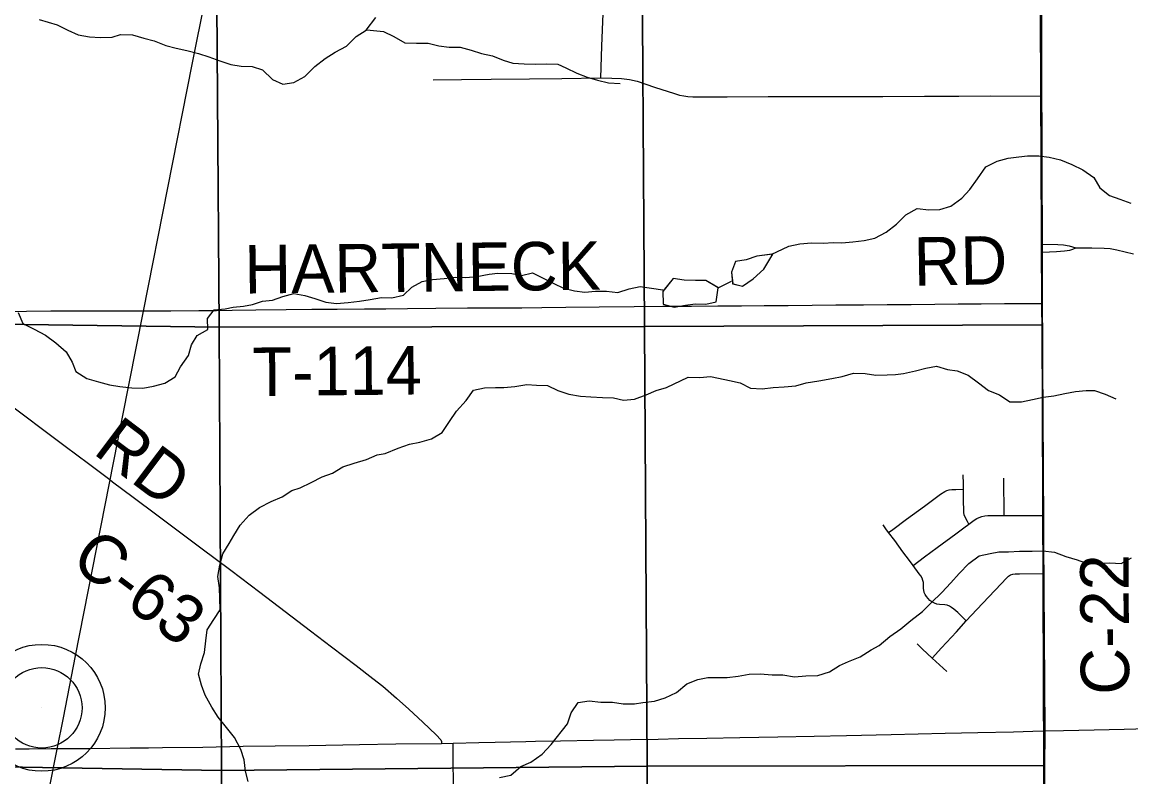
# Model space of a CAD drawing. Extents: x 0 to 34, y 0 to 22.
# Drawn here: x 3.679 to 4.329, y 19.103 to 19.545 of the extents above; entities that cross this region are included whole.
import ezdxf

# ---------------------------------------------------------------- set-up
doc = ezdxf.new("R2010")
doc.units = 0
for name, color, linetype in [('GM_X_County_Road', 7, 'Continuous'), ('GM_X_County_Road_Text', 7, 'Continuous'), ('GM_X_Minor_Lake', 7, 'Continuous'), ('GM_X_Minor_River', 7, 'Continuous'), ('GM_X_Rail_Line', 7, 'Continuous'), ('GM_X_Rail_Line_Text', 7, 'Continuous'), ('GM_X_Section', 7, 'Continuous'), ('GM_X_State_Route', 7, 'Continuous'), ('GM_X_Township', 7, 'Continuous'), ('GM_X_Township_Road', 7, 'Continuous'), ('GM_X_Township_Road_Text', 7, 'Continuous'), ('GM_X_Unincorporated', 7, 'Continuous'), ('GM_X_Unincorporated_Location', 7, 'Continuous')]:
    doc.layers.add(name, color=color, linetype=linetype)

msp = doc.modelspace()

# ---------------------------------------------------------------- linework, layer by layer
at = {"layer": 'GM_X_County_Road'}
for points in [[(4.27842, 19.13012), (4.27823, 19.14942), (4.27809, 19.18871), (4.27797, 19.20548), (4.27788, 19.22223), (4.2778, 19.2563), (4.27762, 19.27909), (4.2775, 19.31971), (4.27734, 19.34088), (4.27721, 19.35817), (4.27715, 19.38057), (4.27709, 19.39599), (4.27715, 19.41065), (4.27709, 19.41525), (4.27698, 19.42412), (4.27692, 19.45257), (4.27688, 19.46599), (4.2768, 19.48305), (4.27668, 19.50205), (4.27661, 19.57053)], [(3.62487, 19.35626), (3.63776, 19.34669), (3.64483, 19.34139), (3.65541, 19.33346), (3.66879, 19.32344), (3.67892, 19.31584), (3.69228, 19.30583), (3.70416, 19.29693), (3.71775, 19.28674), (3.73032, 19.27732), (3.73192, 19.27613)], [(3.73192, 19.27613), (3.74392, 19.26714), (3.75775, 19.25679), (3.7703, 19.24735), (3.78355, 19.23738), (3.80121, 19.22424), (3.81825, 19.21133), (3.83298, 19.20001), (3.84797, 19.18864), (3.86027, 19.17931), (3.87466, 19.16833), (3.88453, 19.16072), (3.89027, 19.15624), (3.89839, 19.14931), (3.90547, 19.14285), (3.9137, 19.1351), (3.92154, 19.12774), (3.9243, 19.12491), (3.92472, 19.12386), (3.92474, 19.12263)], [(4.27851, 19.09573), (4.27854, 19.11102), (4.27846, 19.12439), (4.27842, 19.13012)]]:
    msp.add_lwpolyline(points, dxfattribs=at)
at = {"layer": 'GM_X_Minor_Lake'}
for points in [[(4.11904, 19.40958), (4.10953, 19.40825), (4.10326, 19.40619), (4.09717, 19.40509), (4.09467, 19.39901), (4.09544, 19.39219)], [(4.11839, 19.40949), (4.10953, 19.40825), (4.10326, 19.40619), (4.09717, 19.40509), (4.09467, 19.39901), (4.0954, 19.39254)], [(4.0952, 19.39225), (4.10128, 19.3908), (4.10738, 19.39495), (4.11367, 19.40062), (4.11899, 19.40949)], [(4.09544, 19.39219), (4.10128, 19.3908), (4.10738, 19.39495), (4.11367, 19.40062), (4.11904, 19.40958)], [(4.05456, 19.3879), (4.0547, 19.38021), (4.06115, 19.37846), (4.0678, 19.37957), (4.0735, 19.3803), (4.07977, 19.38026), (4.08585, 19.38156), (4.08687, 19.38968)], [(4.08688, 19.38976), (4.07965, 19.39396), (4.07357, 19.39399), (4.06692, 19.39422), (4.06047, 19.39521), (4.05457, 19.38765)], [(4.05457, 19.38765), (4.0547, 19.38021), (4.06115, 19.37846), (4.0678, 19.37957), (4.0735, 19.3803), (4.07977, 19.38026), (4.08585, 19.38156), (4.08688, 19.38976)], [(4.08667, 19.38988), (4.07965, 19.39396), (4.07357, 19.39399), (4.06692, 19.39422), (4.06047, 19.39521), (4.05476, 19.3879)]]:
    msp.add_lwpolyline(points, dxfattribs=at)
at = {"layer": 'GM_X_Minor_River'}
for points in [[(3.68876, 19.54705), (3.6994, 19.54387), (3.70565, 19.5408), (3.71171, 19.5381), (3.71836, 19.53692), (3.72481, 19.5365), (3.73165, 19.53666), (3.73659, 19.53815), (3.74362, 19.53811), (3.75026, 19.53617), (3.75633, 19.53443), (3.76315, 19.53173), (3.76922, 19.53017), (3.77548, 19.5288), (3.78231, 19.52705), (3.78838, 19.52512), (3.79483, 19.5228), (3.80127, 19.52067), (3.80735, 19.51969), (3.8138, 19.51946), (3.81987, 19.51753), (3.82573, 19.51179), (3.83179, 19.50909), (3.83807, 19.51001), (3.84454, 19.51359), (3.85046, 19.51945), (3.85656, 19.52417), (3.86247, 19.52794), (3.86894, 19.53133), (3.87467, 19.53701), (3.88057, 19.54078), (3.88623, 19.5482)], [(3.88088, 19.54097), (3.89064, 19.53996), (3.8967, 19.53708), (3.90314, 19.53343), (3.90998, 19.5332), (3.91681, 19.53316), (3.92307, 19.5316), (3.92915, 19.53081), (3.9356, 19.53077), (3.94205, 19.52903), (3.94812, 19.52709), (3.95457, 19.52572), (3.96083, 19.52321), (3.96651, 19.52147), (3.97316, 19.52105), (3.97962, 19.52083), (3.98646, 19.52098), (3.99291, 19.52075), (3.99765, 19.51864), (4.00409, 19.51556), (4.01016, 19.51324), (4.01623, 19.51149), (4.02268, 19.50994), (4.02951, 19.50952)], [(4.11799, 19.40929), (4.12837, 19.41424), (4.13483, 19.41553), (4.14167, 19.41606), (4.14851, 19.41603), (4.15459, 19.41637), (4.15934, 19.41616), (4.1658, 19.41669), (4.17245, 19.41742), (4.17872, 19.4189), (4.18539, 19.42229), (4.19149, 19.42701), (4.19702, 19.4325), (4.2035, 19.43627), (4.21052, 19.43547), (4.21698, 19.43562), (4.22326, 19.43768), (4.22974, 19.4424), (4.23451, 19.44732), (4.23891, 19.45357), (4.24389, 19.46058), (4.25055, 19.46397), (4.25702, 19.46584), (4.26329, 19.46656), (4.26823, 19.46711), (4.27488, 19.46707), (4.28095, 19.46628), (4.28759, 19.46472), (4.29422, 19.46202), (4.30067, 19.45894), (4.3071, 19.45434), (4.31068, 19.44842), (4.31635, 19.44382), (4.32242, 19.4417), (4.32887, 19.43938)], [(3.9024, 19.38543), (3.90736, 19.39016), (3.91346, 19.39355), (3.91954, 19.39466), (3.92638, 19.39519), (3.93284, 19.3961), (3.93892, 19.39588), (3.94538, 19.39641), (3.9526, 19.39771), (3.95773, 19.39844), (3.9659, 19.3982), (3.97159, 19.39703), (3.97806, 19.39852), (3.98393, 19.39563), (3.99056, 19.39236), (3.99624, 19.38948), (4.00269, 19.38792), (4.00877, 19.38712), (4.01504, 19.38785), (4.0215, 19.38781), (4.02814, 19.38702), (4.0348, 19.38907), (4.04126, 19.39056), (4.05456, 19.3885)], [(4.08687, 19.38968), (4.0948, 19.39364)], [(3.67653, 19.37526), (3.67934, 19.36878), (3.68597, 19.36551), (3.6926, 19.36205), (3.69866, 19.35745), (3.70471, 19.35228), (3.7081, 19.34617), (3.71035, 19.34064), (3.71679, 19.33661), (3.72362, 19.33467), (3.73006, 19.33293), (3.73614, 19.33194), (3.74316, 19.33114), (3.74962, 19.33091), (3.75589, 19.33221), (3.76255, 19.33389), (3.76864, 19.33766), (3.77171, 19.34354), (3.7763, 19.35017), (3.77823, 19.35625), (3.78149, 19.36175), (3.78777, 19.36533), (3.78762, 19.3718), (3.79144, 19.37691), (3.7979, 19.37744), (3.80265, 19.37837), (3.80873, 19.3791), (3.81387, 19.38002), (3.81976, 19.38189), (3.82565, 19.38262), (3.83174, 19.38468), (3.83821, 19.38635), (3.84466, 19.38518), (3.85054, 19.38343), (3.85699, 19.3813), (3.86325, 19.38051), (3.87009, 19.38123), (3.87674, 19.38196), (3.88283, 19.38287), (3.88948, 19.38417), (3.89556, 19.38394), (3.9024, 19.38543)], [(3.81133, 19.10039), (3.80984, 19.10649), (3.80893, 19.11315), (3.80706, 19.11925), (3.80329, 19.12612), (3.79876, 19.13204), (3.79386, 19.13816), (3.79009, 19.14407), (3.78614, 19.15094), (3.78407, 19.15685), (3.78221, 19.16333), (3.78357, 19.16941), (3.78569, 19.17606), (3.78648, 19.1829), (3.78728, 19.18936), (3.79129, 19.19543), (3.79493, 19.20112), (3.79477, 19.20759), (3.79462, 19.21386), (3.79351, 19.22053), (3.79468, 19.22718), (3.79661, 19.23383), (3.80025, 19.23989), (3.80294, 19.24464), (3.80676, 19.2507), (3.81192, 19.25657), (3.81802, 19.26091), (3.82488, 19.26449), (3.83135, 19.26731), (3.83706, 19.27089), (3.84182, 19.27257), (3.84829, 19.27558), (3.85477, 19.27897), (3.86086, 19.28122), (3.86695, 19.2848), (3.87342, 19.28705), (3.88065, 19.2891), (3.88693, 19.29192), (3.89168, 19.29265), (3.89929, 19.29585), (3.90595, 19.29809), (3.91204, 19.29939), (3.91888, 19.30125), (3.92517, 19.30502), (3.92938, 19.31147), (3.93359, 19.31753), (3.93913, 19.32378), (3.94353, 19.32984), (3.94999, 19.33114), (3.95645, 19.33129), (3.9612, 19.33127), (3.96766, 19.33199), (3.97469, 19.3331), (3.98039, 19.33268), (3.98684, 19.33246), (3.99291, 19.32957), (3.99935, 19.32744), (4.00618, 19.32626), (4.01226, 19.32585), (4.0191, 19.32543), (4.02555, 19.3252), (4.03143, 19.32384), (4.03789, 19.32457), (4.04474, 19.327), (4.05065, 19.32963), (4.05673, 19.33131), (4.0693, 19.33733), (4.07613, 19.33729), (4.0824, 19.33783), (4.08715, 19.33685), (4.0936, 19.33548), (4.09986, 19.33412), (4.10592, 19.33104), (4.11276, 19.33062), (4.11922, 19.33134), (4.12568, 19.33169), (4.13252, 19.33222), (4.1386, 19.33409), (4.14602, 19.33519), (4.15362, 19.33667), (4.1597, 19.33778), (4.16636, 19.33983), (4.1732, 19.33961), (4.17946, 19.33862), (4.18592, 19.33877), (4.19086, 19.33894), (4.19561, 19.33948), (4.20264, 19.34116), (4.20873, 19.34264), (4.215, 19.34375)], [(4.215, 19.34375), (4.22145, 19.34181), (4.22714, 19.34102), (4.23359, 19.33851), (4.23965, 19.3341), (4.24551, 19.3295), (4.25195, 19.327), (4.25801, 19.32297), (4.26485, 19.32293), (4.27131, 19.32423), (4.2774, 19.32571), (4.28367, 19.32644), (4.29013, 19.32774), (4.29641, 19.32903), (4.30268, 19.32957), (4.30762, 19.32954), (4.31387, 19.32741), (4.32013, 19.32472)], [(3.95873, 19.10281), (3.96538, 19.10411), (3.9713, 19.10921), (3.97719, 19.11165), (3.98368, 19.11637), (3.98902, 19.12205), (3.99858, 19.13417), (4.0007, 19.14063), (4.00491, 19.14669), (4.01137, 19.14761), (4.01821, 19.147), (4.02504, 19.14696), (4.03131, 19.14597), (4.03795, 19.14594), (4.0427, 19.14667), (4.04955, 19.14759), (4.05582, 19.14945), (4.06249, 19.15265), (4.06859, 19.15775), (4.07506, 19.16019), (4.08095, 19.1613), (4.08741, 19.16145), (4.09216, 19.16143), (4.09862, 19.16215), (4.10508, 19.16326), (4.11154, 19.1636), (4.11857, 19.16299), (4.12483, 19.16296), (4.13167, 19.16178), (4.13832, 19.16231), (4.14534, 19.16246), (4.15219, 19.16471), (4.1581, 19.16848), (4.16343, 19.17073), (4.17009, 19.17355), (4.17657, 19.17751), (4.18133, 19.18015), (4.18762, 19.18544), (4.1941, 19.18997), (4.19982, 19.19469), (4.20669, 19.19998), (4.21184, 19.20509), (4.21814, 19.21114), (4.2233, 19.21682), (4.22826, 19.22231), (4.2338, 19.22818), (4.2399, 19.23271), (4.24636, 19.234), (4.2515, 19.23512), (4.25719, 19.23508), (4.26365, 19.23543), (4.27106, 19.23539), (4.27733, 19.23554), (4.28416, 19.23475), (4.2908, 19.23223), (4.29743, 19.2303), (4.30331, 19.22817), (4.30977, 19.22813), (4.31661, 19.22848), (4.32325, 19.22825), (4.32935, 19.23145)]]:
    msp.add_lwpolyline(points, dxfattribs=at)
at = {"layer": 'GM_X_Rail_Line'}
msp.add_lwpolyline([(3.68321, 18.51252), (3.68335, 18.52615), (3.68363, 18.60767), (3.68539, 18.8321), (3.68546, 18.87311), (3.68595, 18.92557), (3.68616, 18.95267), (3.68616, 18.97444), (3.68667, 19.02131), (3.6878, 19.04242), (3.68925, 19.05702), (3.69052, 19.0684), (3.69255, 19.08272), (3.69485, 19.09663), (3.69943, 19.11938), (3.70316, 19.13778), (3.71011, 19.17401), (3.73756, 19.31305), (3.74992, 19.37604), (3.77857, 19.5207), (3.78644, 19.55974)], dxfattribs=at)
at = {"layer": 'GM_X_Rail_Line_Text'}
msp.add_lwpolyline([(2.77875, 17.80661), (3.04126, 17.80913), (3.53178, 17.8199), (4.04512, 17.83208), (4.17864, 17.83524), (4.28678, 17.83811), (4.28692, 17.84212), (4.28581, 17.95524), (4.28464, 18.15407), (4.27642, 18.36992), (4.27726, 18.56476), (4.27587, 18.8261), (4.27859, 19.13014), (4.27679, 19.3807), (4.2769, 19.4129), (4.27672, 19.50175), (4.27627, 19.60888)], dxfattribs=at)
at = {"layer": 'GM_X_Section'}
for points in [[(3.79246, 19.63723), (3.79428, 19.36662), (3.53702, 19.37026), (3.53581, 19.63725)], [(4.04196, 19.63655), (4.0438, 19.36716), (3.79428, 19.36662), (3.79246, 19.63723)], [(4.27537, 19.63561), (4.27657, 19.37662), (4.2766, 19.36802), (4.0438, 19.36716), (4.04196, 19.63655)], [(3.79428, 19.36662), (3.79582, 19.10682), (3.53903, 19.11114), (3.53702, 19.37026)], [(4.0438, 19.36716), (4.04538, 19.10932), (3.79582, 19.10682), (3.79428, 19.36662)], [(4.2766, 19.36802), (4.2777, 19.10976), (4.04538, 19.10932), (4.0438, 19.36716)], [(3.79582, 19.10682), (3.79726, 18.85283), (3.54138, 18.85346), (3.53903, 19.11114)], [(4.2777, 19.10976), (4.27852, 18.86654), (4.27864, 18.85366), (4.04732, 18.85326), (4.04538, 19.10932)], [(4.04538, 19.10932), (4.04732, 18.85326), (3.79726, 18.85283), (3.79582, 19.10682)]]:
    msp.add_lwpolyline(points, close=True, dxfattribs=at)
at = {"layer": 'GM_X_State_Route'}
for points in [[(3.67491, 19.11947), (3.68295, 19.11962), (3.6959, 19.11967), (3.69926, 19.1197), (3.7024, 19.11974), (3.71847, 19.11984), (3.7421, 19.12011), (3.75303, 19.12024), (3.76113, 19.12028), (3.78473, 19.12059), (3.80836, 19.1211), (3.82722, 19.12127), (3.8471, 19.12161), (3.87673, 19.12219), (3.8979, 19.12249), (3.92474, 19.12263), (3.93154, 19.12288), (3.94658, 19.12319), (3.95615, 19.12341), (3.96526, 19.12363), (3.97417, 19.12383), (3.97984, 19.12397), (3.99456, 19.12431), (4.01374, 19.12464), (4.026, 19.12478), (4.03549, 19.12501), (4.05178, 19.12532), (4.06363, 19.12555), (4.0802, 19.12582), (4.09968, 19.12614), (4.12192, 19.1266), (4.14317, 19.12701), (4.16224, 19.12741), (4.18839, 19.128), (4.21994, 19.12882), (4.23917, 19.12916), (4.26011, 19.1296), (4.27144, 19.1299), (4.27842, 19.13012)], [(4.27842, 19.13012), (4.28945, 19.13036), (4.30729, 19.13076), (4.32499, 19.13111), (4.34555, 19.13174)]]:
    msp.add_lwpolyline(points, dxfattribs=at)
at = {"layer": 'GM_X_Township'}
msp.add_lwpolyline([(5.23962, 17.86489), (4.75674, 17.85444), (4.28987, 17.8422), (4.28692, 17.84212), (4.28581, 17.95524), (4.28464, 18.15407), (4.27642, 18.36992), (4.27726, 18.56476), (4.27587, 18.8261), (4.27859, 19.13014), (4.27679, 19.3807), (4.2769, 19.4129), (4.27672, 19.50175), (4.27627, 19.60888)], dxfattribs=at)
at = {"layer": 'GM_X_Township_Road'}
msp.add_line((4.25451, 19.25637), (4.25447, 19.27827), dxfattribs=at)
for points in [[(4.01805, 19.51279), (4.01872, 19.53135), (4.01943, 19.5506), (4.02012, 19.56975), (4.02083, 19.5889), (4.02139, 19.60443), (4.02167, 19.61794), (4.02193, 19.63111), (4.02182, 19.64413), (4.02159, 19.66112), (4.0214, 19.67489), (4.02118, 19.69159), (4.02095, 19.70838), (4.02074, 19.72391), (4.02055, 19.73845)], [(3.91977, 19.51167), (3.9364, 19.51186), (3.95382, 19.51206), (3.97638, 19.51231), (3.99526, 19.51253), (4.01805, 19.51279), (4.02453, 19.51261), (4.0302, 19.51247), (4.03502, 19.51184), (4.03942, 19.51083), (4.04961, 19.50745), (4.0613, 19.50357), (4.06416, 19.50275), (4.06675, 19.50226), (4.06911, 19.50198), (4.07215, 19.50176), (4.07683, 19.50163), (4.09221, 19.5017), (4.11633, 19.50182), (4.15693, 19.5019), (4.18347, 19.50197), (4.20787, 19.50203), (4.22812, 19.50212), (4.2468, 19.50221), (4.27668, 19.50205)], [(4.27709, 19.41525), (4.28603, 19.41517), (4.28945, 19.41489), (4.29271, 19.41444), (4.29473, 19.41387), (4.29664, 19.41315)], [(4.27715, 19.41065), (4.28524, 19.411), (4.29007, 19.41144), (4.29302, 19.41185), (4.29483, 19.41237), (4.29664, 19.41315)], [(4.29664, 19.41315), (4.30099, 19.4132), (4.30591, 19.41325), (4.3132, 19.41304), (4.31678, 19.41273), (4.32064, 19.41205), (4.32549, 19.41094), (4.33036, 19.40975)], [(3.6695, 19.37579), (3.68135, 19.37602), (3.69574, 19.37622), (3.75003, 19.37622), (3.76598, 19.37631), (3.78236, 19.37641), (3.7929, 19.3765), (3.80191, 19.37659), (3.81577, 19.37677), (3.83356, 19.37699), (3.84875, 19.37718), (3.8635, 19.3773), (3.87963, 19.37744), (3.89204, 19.37753), (3.90487, 19.37762), (3.92133, 19.37779), (3.94004, 19.37798), (3.95347, 19.37803), (3.97176, 19.3781), (3.98351, 19.37822), (3.99757, 19.37835), (4.01723, 19.3786), (4.03773, 19.37885), (4.05442, 19.37894), (4.07126, 19.37904), (4.08674, 19.37916), (4.10057, 19.37927), (4.11383, 19.37937), (4.12788, 19.37948), (4.14197, 19.3796), (4.15598, 19.37971), (4.17218, 19.37983), (4.18601, 19.37995), (4.20006, 19.38006), (4.21398, 19.38017), (4.2276, 19.38028), (4.24109, 19.38042), (4.25487, 19.38057), (4.27715, 19.38057)], [(4.23393, 19.25133), (4.23312, 19.25285), (4.23162, 19.25568), (4.23118, 19.2567), (4.23091, 19.25802), (4.23087, 19.25917), (4.23081, 19.26487), (4.23074, 19.27167), (4.2307, 19.27495), (4.23064, 19.28021)], [(4.18686, 19.2464), (4.18927, 19.24817), (4.19741, 19.25415), (4.20785, 19.26182), (4.21728, 19.26875), (4.21982, 19.27045), (4.22101, 19.27106), (4.22238, 19.27141), (4.22393, 19.27155), (4.22631, 19.27159), (4.23074, 19.27167)], [(4.20122, 19.22707), (4.20794, 19.23204), (4.21528, 19.23747), (4.22617, 19.24553), (4.231, 19.24914), (4.23393, 19.25133), (4.23695, 19.25358), (4.23865, 19.25458), (4.24002, 19.25524), (4.24152, 19.25573), (4.24324, 19.25608), (4.24501, 19.2563), (4.24815, 19.25638), (4.25451, 19.25637), (4.27353, 19.25631), (4.2778, 19.2563)], [(4.23238, 19.19462), (4.22736, 19.19944), (4.22505, 19.20145), (4.22369, 19.20246), (4.22258, 19.20312), (4.22117, 19.20367), (4.21975, 19.20397), (4.21673, 19.20418), (4.21517, 19.20443), (4.21371, 19.20488), (4.21229, 19.20564), (4.21108, 19.20654), (4.20902, 19.20886), (4.20831, 19.21007), (4.20771, 19.21128), (4.20735, 19.2137), (4.20725, 19.21698), (4.20695, 19.21824), (4.20645, 19.21965), (4.20569, 19.22101), (4.20478, 19.22222), (4.20122, 19.22707), (4.1991, 19.22995), (4.19521, 19.23512), (4.19045, 19.24158), (4.18686, 19.2464), (4.18529, 19.2485), (4.18361, 19.25075)], [(4.21233, 19.17269), (4.21779, 19.17866), (4.22664, 19.18823), (4.23238, 19.19462), (4.23862, 19.20122), (4.24569, 19.2087), (4.25282, 19.21634), (4.25599, 19.21968), (4.25712, 19.22071), (4.25827, 19.22148), (4.25964, 19.22194), (4.261, 19.2221), (4.26369, 19.2222), (4.27788, 19.22223)], [(4.22107, 19.16495), (4.21675, 19.16878), (4.21233, 19.17269), (4.20679, 19.17794), (4.20354, 19.18102)], [(3.9314, 18.843), (3.9323, 18.84684), (3.93336, 18.85255), (3.9343, 18.86377), (3.9345, 18.86716), (3.93457, 18.87654), (3.93423, 18.88725), (3.9335, 18.90634), (3.93306, 18.92615), (3.93291, 18.94312), (3.9327, 18.95457), (3.93239, 18.97104), (3.93211, 18.98582), (3.93193, 19.00651), (3.93178, 19.02262), (3.93169, 19.04339), (3.93162, 19.05781), (3.93168, 19.07115), (3.93174, 19.08719), (3.93178, 19.09897), (3.93164, 19.11273), (3.93154, 19.12288)]]:
    msp.add_lwpolyline(points, dxfattribs=at)
at = {"layer": 'GM_X_Unincorporated'}
for radius in [0.0372, 0.02358]:
    msp.add_circle((3.69038, 19.14359), radius, dxfattribs=at)
at = {"layer": 'GM_X_Unincorporated_Location'}
msp.add_line((3.69038, 19.14359), (3.69038, 19.14359), dxfattribs=at)

# ---------------------------------------------------------------- texts
at = {"layer": 'GM_X_County_Road_Text'}
for s, rotation, p in [('RD', 323.03134, (3.71971, 19.29302)), ('C-63', 323.26736, (3.70618, 19.22773)), ('C-22', 90.3429, (4.32798, 19.15133))]:
    msp.add_text(s, height=0.028409, rotation=rotation, dxfattribs=at).set_placement(p)
at = {"layer": 'GM_X_Township_Road_Text'}
for s, rotation, p in [('HARTNECK', 0.63082, (3.8093, 19.38638)), ('RD', 0.98721, (4.20176, 19.39096)), ('T-114', 0.56142, (3.81404, 19.32632))]:
    msp.add_text(s, height=0.028409, rotation=rotation, dxfattribs=at).set_placement(p)

doc.saveas('drawing.dxf')
